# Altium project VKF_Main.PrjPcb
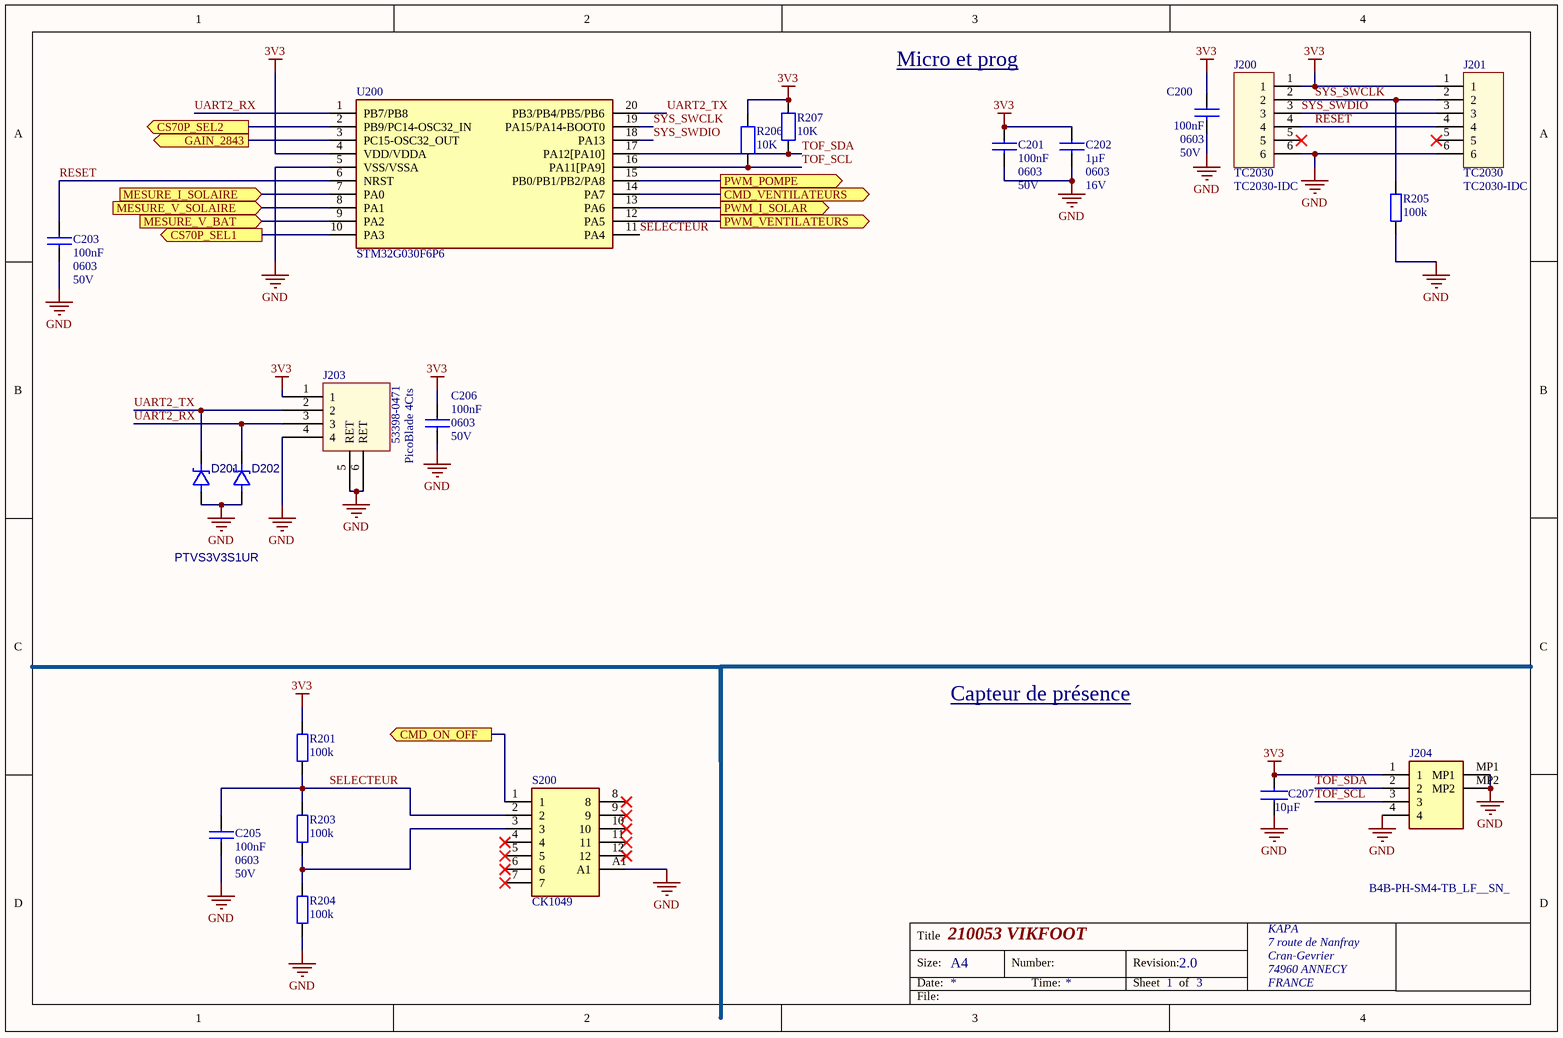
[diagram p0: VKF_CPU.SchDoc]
3 sheets, 104 parts. Net scope: flat (ports and power ports of the same name join across sheets).
Board file: VKF_PCB.PcbDoc
Sheets:
  VKF_CPU.SchDoc
  VKF_SOLAIRE.SchDoc
  VKF_ALIM.SchDoc

## Sheet VKF_CPU.SchDoc: DEV-09-17 MERE
size A4; Date: 22/11/2017; Organization: Altium Limited; Address1: L3, 12a Rodborough Rd; Address2: Frenchs Forest; Address3: NSW; Address4: Australia 2086; DocumentNumber: 4; Revision: 2.0; SheetNumber: 1; SheetTotal: 3; PageSetup: Record=PageOptions¦CenterHorizontal=True¦CenterVertical=True¦PrintScale=0.97¦XCorrection=1.00¦YCorrection=1.00¦PrintKind=0¦BorderSize=5000000¦LeftOffset=0¦BottomOffset=0¦Orientation=2¦PaperLength=1000¦PaperWidth=1000¦Scale=100¦PaperSource=7¦PrintQuality=-3¦MediaType=1¦DitherType=10¦PaperKind=A4¦PrintScaleMode=1

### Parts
C200  100nF  CASE: 0603  Voltage: 50V  [CAP0603]
C201  100nF  CASE: 0603  Voltage: 50V  [CAP0603]
C202  1µF  CASE: 0603  Voltage: 16V  [CAP0603]
C203  100nF  CASE: 0603  Voltage: 50V  [CAP0603]
C205  100nF  CASE: 0603  Voltage: 50V  [CAP0603]
C206  100nF  CASE: 0603  Voltage: 50V  [CAP0603]
C207  10µF  [CAP_0603_0H80]
D201  PTVS3V3S1UR  [SOD-123]
D202  PTVS3V3S1UR  [SOD-123]  (value not drawn)
J200  TC2030  CASE: TC2030-IDC  [TC2030-IDC-FP]
J201  TC2030  CASE: TC2030-IDC  [TC2030-IDC-FP]
J203  53398-0471  CASE: PicoBlade 4Cts  [CNT-S (MOLEX Ref SD-53398-0471)]
J204  B4B-PH-SM4-TB_LF__SN_  [B4B-PH-SM4_1]
R201  100k  [RES0603]
R203  100k  [RES0603]
R204  100k  [RES0603]
R205  100k  [RES0603]
R206  10K  [RES_0603_0H90]
R207  10K  [RES_0603_0H90]
S200  CK1049  [CK1059]
U200  STM32G030F6P6  [TSSOP20-0.65]

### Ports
CMD_ON_OFF (out, see VKF_SOLAIRE[1B]), CMD_VENTILATEURS (out, see VKF_ALIM[3B]), CS70P_SEL1 (out, see VKF_SOLAIRE[2A]), CS70P_SEL2 (out, see VKF_SOLAIRE[2A]), GAIN_2843 (out, see VKF_SOLAIRE[4C]), MESURE_I_SOLAIRE (in, see VKF_SOLAIRE[3A]), MESURE_V_BAT (in, see VKF_SOLAIRE[4A]), MESURE_V_SOLAIRE (in, see VKF_SOLAIRE[3A]), PWM_I_SOLAR (out, see VKF_SOLAIRE[2B]), PWM_POMPE (out, see VKF_ALIM[3C]), PWM_VENTILATEURS (out, see VKF_ALIM[3B])

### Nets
3V3: C200.1 C201.1 C202.1 C206.1 C207.2 J200.1 J201.1 J203.1 J204.1 R201.2 R206.2 R207.2 U200.4(VDD/VDDA)
GND: C200.2 C201.2 C202.2 C203.2 C205.2 C206.2 C207.1 D201.2(A) D202.2(A) J200.6 J201.6 J203.4 J203.5(RET) J203.6(RET) J204.4 J204.MP1 J204.MP2 R204.1 R205.1 S200.A1 U200.5(VSS/VSSA)
RESET: C203.1 J200.4 J201.4 U200.6(NRST)
SELECTEUR: C205.1 R201.1 R203.2 S200.2 U200.11(PA4)
SYS_SWCLK: J200.2 J201.2 R205.2 U200.19(PA15/PA14-BOOT0)
SYS_SWDIO: J200.3 J201.3 U200.18(PA13)
TOF_SCL: J204.3 R206.1 U200.16(PA11[PA9])
TOF_SDA: J204.2 R207.1 U200.17(PA12[PA10])
UART2_RX: D202.1(K) J203.3 U200.1(PB7/PB8)
UART2_TX: D201.1(K) J203.2 U200.20(PB3/PB4/PB5/PB6)
NetC300_1: U200.8(PA1) ; port MESURE_V_SOLAIRE
NetC301_1: U200.9(PA2) ; port MESURE_V_BAT
NetC303_1: U200.7(PA0) ; port MESURE_I_SOLAIRE
NetD302_3: S200.1 ; port CMD_ON_OFF
NetIC102_3: U200.15(PB0/PB1/PB2/PA8) ; port PWM_POMPE
NetIC300_2: U200.10(PA3) ; port CS70P_SEL1
NetIC300_3: U200.2(PB9/PC14-OSC32_IN) ; port CS70P_SEL2
NetQ101_1: U200.12(PA5) ; port PWM_VENTILATEURS
NetQ102_1: U200.14(PA7) ; port CMD_VENTILATEURS
NetR203_1: R203.1 R204.2 S200.3
NetR306_1: U200.13(PA6) ; port PWM_I_SOLAR
NetR312_2: U200.3(PC15-OSC32_OUT) ; port GAIN_2843

Not connected (* = marked no-connect by the designer): J200 5*; J201 5*; S200 4* 5* 6* 7* 8* 9* 10* 11* 12*

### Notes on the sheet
- Micro et prog
- Capteur de présence
- Title
- Size:
- Date:
- 210053 VIKFOOT
- A4
- Number:
- Time:
- Revision:
- Sheet
- of
- KAPA
- 7 route de Nanfray
- 74960 ANNECY
- Cran-Gevrier
- FRANCE
- File:

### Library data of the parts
C200 C201 C203 C205 C206 = C0603-100nF-X7R-50V: Capacitor, Ceramic, 100nF, 0603, 10%, 50V, X7R; Ref Fabricant: Generic
C202 = C0603-1µF-X7R-16V: Capacitor, Ceramic, 1µF, 0603, 10%, 16V, X7R; Ref Fabricant: Generic
C207 = capacitor
D201 D202 = PTVS3V3S1UR: Diode TVS, série PTVS, 3.3 V, SOD-123; Prix: 0.363 €; Fabricant: NXP; Fournisseur: Farnell; Ref Fournisseur: 1829253
J200 J201 = TC2030: Connector Sonde Probe, 6cts; Fabricant: TAG-CONNECT; Ref Fournisseur: none
J203 = CNT-MOLEX-PicoBlade-SMT-4cts: Connector PicoBlade Header, SMT, 4cts; Fabricant: MOLEX; Ref Fournisseur: 1125367; Fournisseur: Farnell
J204 = B4B-PH-SM4-TB_LF__SN_: Connector; Manufacturer_Name: JST (JAPAN SOLDERLESS TERMINALS); Manufacturer_Part_Number: B4B-PH-SM4-TB(LF)(SN)
R201 R203-R205 = R0603_100k_1%_1: Resistor, Thin Film, 100k, 1%, 65mW, 0603; Ref Fabricant: Generic; TCR: 100ppm/°C
R206 R207 = Resistor
S200 = CK1049: Switch; Manufacturer_Name: Lorlin
U200 = STM32G030F6P6: ARM Cortex-M0+ 32-bit MCU, 32 KB Flash, 8 KB Internal RAM, 20-pin TSSOP; Fabricant: STMicroelectronics; Ref Fournisseur: 511-STM32G030F6P6; Fournisseur: Mouser

## Sheet VKF_SOLAIRE.SchDoc: DEV-09-17 MERE
size A4; Date: 22/11/2017; Organization: Altium Limited; Address1: L3, 12a Rodborough Rd; Address2: Frenchs Forest; Address3: NSW; Address4: Australia 2086; DocumentNumber: 4; Revision: 2.0; SheetNumber: 2; SheetTotal: 3; PageSetup: Record=PageOptions¦CenterHorizontal=True¦CenterVertical=True¦PrintScale=0.97¦XCorrection=1.00¦YCorrection=1.00¦PrintKind=0¦BorderSize=5000000¦LeftOffset=0¦BottomOffset=0¦Orientation=2¦PaperLength=1000¦PaperWidth=1000¦Scale=100¦PaperSource=7¦PrintQuality=-3¦MediaType=1¦DitherType=10¦PaperKind=A4¦PrintScaleMode=1
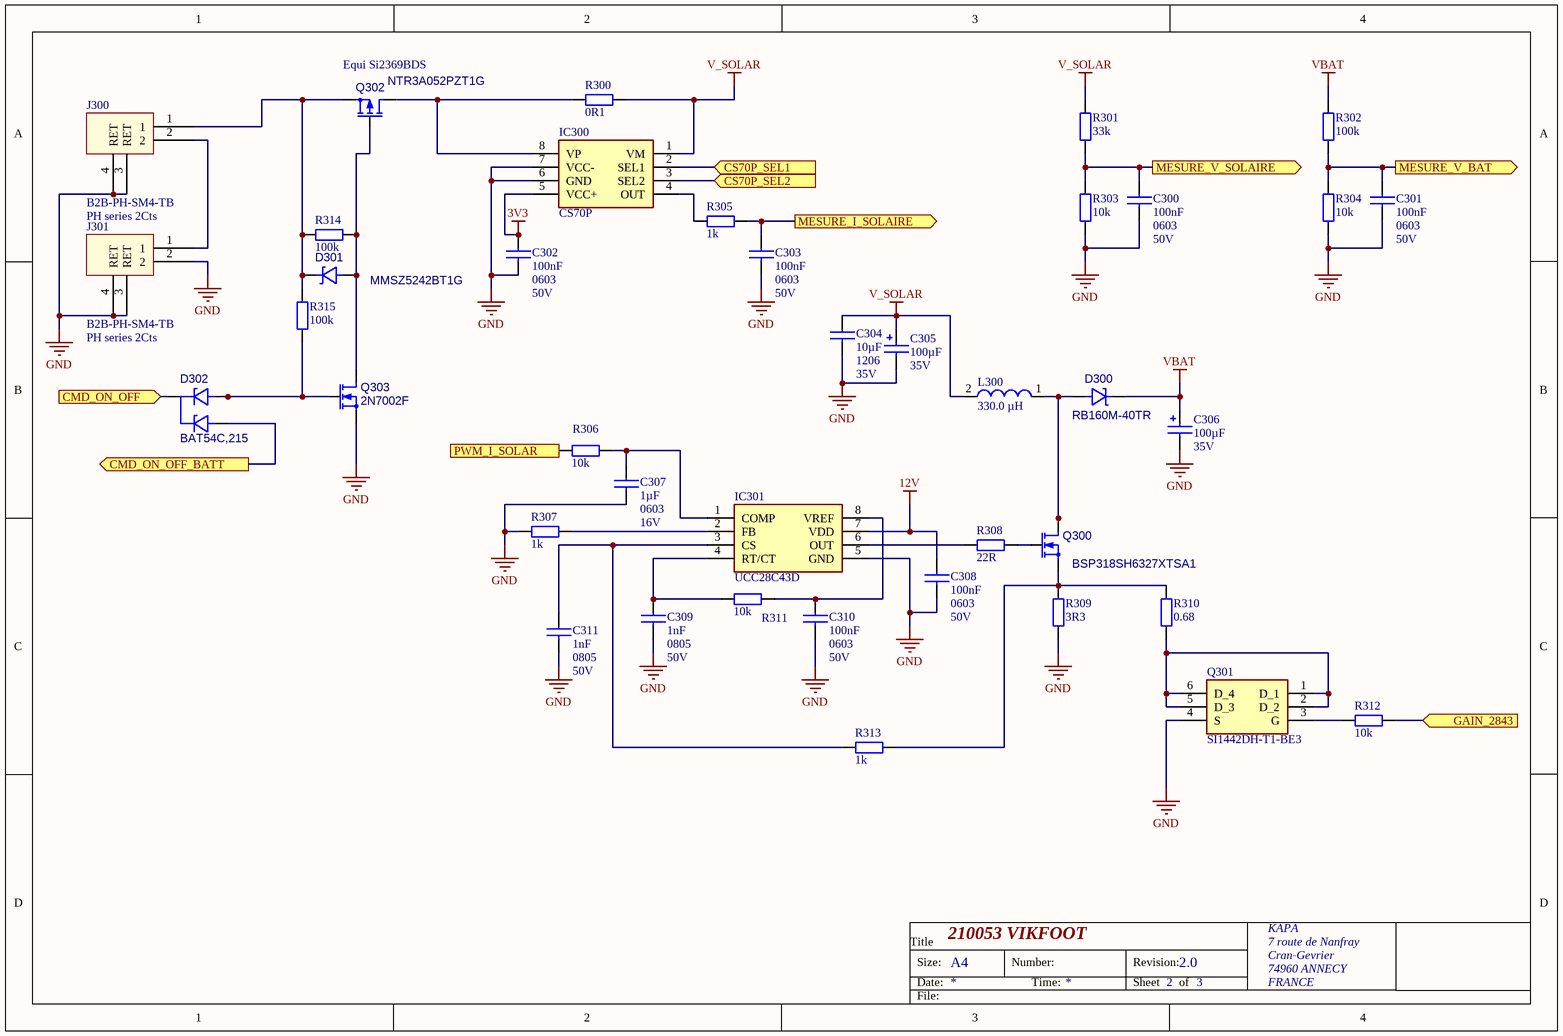
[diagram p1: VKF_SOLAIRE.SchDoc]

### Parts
C300  100nF  CASE: 0603  Voltage: 50V  [CAP0603]
C301  100nF  CASE: 0603  Voltage: 50V  [CAP0603]
C302  100nF  CASE: 0603  Voltage: 50V  [CAP0603]
C303  100nF  CASE: 0603  Voltage: 50V  [CAP0603]
C304  10µF  CASE: 1206  Voltage: 35V  [CAP1206]
C305  100µF  Voltage: 35V  [CP_D8]
C306  100µF  Voltage: 35V  [CP_D8]
C307  1µF  CASE: 0603  Voltage: 16V  [CAP0603]
C308  100nF  CASE: 0603  Voltage: 50V  [CAP0603]
C309  1nF  CASE: 0805  Voltage: 50V  [CAP0805]
C310  100nF  CASE: 0603  Voltage: 50V  [CAP0603]
C311  1nF  CASE: 0805  Voltage: 50V  [CAP0805]
D300  RB160M-40TR  [SOD-123]
D301  MMSZ5242BT1G  [SOD-123]
D302  BAT54C,215  [SOT23]
IC300  CS70P  [SOP65P640X120-8N]
IC301  UCC28C43D  [SOIC127P600X175-8N]
J300  B2B-PH-SM4-TB  CASE: PH series 2Cts  [CNT-S (JST Ref B2B-PH-SM4)]
J301  B2B-PH-SM4-TB  CASE: PH series 2Cts  [CNT-S (JST Ref B2B-PH-SM4)]
L300  330.0 µH  [WE-PD-M-PB]
Q300  BSP318SH6327XTSA1  [ONSC-SOT-223-4-318E-04_V]
Q301  SI1442DH-T1-BE3  [SOT65P210X110-6N]
Q302  NTR3A052PZT1G  [SOT23]
Q303  2N7002F  [SOT23]
R300  0R1  [RES0805]
R301  33k  [RES0603]
R302  100k  [RES0603]
R303  10k  [RES0603]
R304  10k  [RES0603]
R305  1k  [RES0805]
R306  10k  [RES0805]
R307  1k  [RES0805]
R308  22R  [RES0805]
R309  3R3  [RES0805]
R310  0.68  [RES1206]
R311  10k  [RES0805]
R312  10k  [RES0603]
R313  1k  [RES0805]
R314  100k  [RES0603]
R315  100k  [RES0603]

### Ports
CMD_ON_OFF (in, see VKF_CPU[1C]), CMD_ON_OFF_BATT (out, see VKF_ALIM[1D]), CS70P_SEL1 (in, see VKF_CPU[1A]), CS70P_SEL2 (in, see VKF_CPU[1A]), GAIN_2843 (in, see VKF_CPU[1A]), MESURE_I_SOLAIRE (out, see VKF_CPU[1A]), MESURE_V_BAT (out, see VKF_CPU[1A]), MESURE_V_SOLAIRE (out, see VKF_CPU[1A]), PWM_I_SOLAR (in, see VKF_CPU[2A])

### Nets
3V3: C302.1 IC300.5(VCC+)
12V: C308.1 IC301.7(VDD)
GND: C300.2 C301.2 C302.2 C303.2 C304.2 C305.2 C306.2 C307.2 C308.2 C309.2 C310.2 C311.2 IC300.6(GND) IC300.7(VCC-) IC301.5(GND) J300.3(RET) J300.4(RET) J301.2 J301.3(RET) J301.4(RET) Q301.4(S) Q303.2(S) R303.1 R304.1 R307.1 R309.1
V_SOLAR: C304.1 C305.1 IC300.1(VM) L300.2 R300.2 R301.2
VBAT: C306.1 D300.1(K) R302.2
NetC300_1: C300.1 R301.1 R303.2 ; port MESURE_V_SOLAIRE
NetC301_1: C301.1 R302.1 R304.2 ; port MESURE_V_BAT
NetC303_1: C303.1 R305.2 ; port MESURE_I_SOLAIRE
NetC307_1: C307.1 IC301.1(COMP) R306.2
NetC309_1: C309.1 IC301.4(RT/CT) R311.1
NetC310_1: C310.1 IC301.8(VREF) R311.2
NetC311_1: C311.1 IC301.3(CS) R313.1
NetD300_2: D300.2(A) L300.1 Q300.2(D) Q300.4(D)
NetD301_1: D301.1(K) J300.1 Q302.2(S) R314.2 R315.2
NetD301_2: D301.2(A) Q302.1(G) Q303.3(D) R314.1
NetD302_1: D302.1(K1) Q303.1(G) R315.1
NetD302_2: D302.2(K2) ; port CMD_ON_OFF_BATT
NetD302_3: D302.3(A) ; port CMD_ON_OFF
NetIC300_2: IC300.2(SEL1) ; port CS70P_SEL1
NetIC300_3: IC300.3(SEL2) ; port CS70P_SEL2
NetIC300_4: IC300.4(OUT) R305.1
NetIC300_8: IC300.8(VP) Q302.3(D) R300.1
NetIC301_2: IC301.2(FB) R307.2
NetIC301_6: IC301.6(OUT) R308.1
NetJ300_2: J300.2 J301.1
NetQ300_1: Q300.1(G) R308.2
NetQ300_3: Q300.3(S) R309.2 R310.2 R313.2
NetQ301_1: Q301.1(D_1) Q301.2(D_2) Q301.5(D_3) Q301.6(D_4) R310.1
NetQ301_3: Q301.3(G) R312.1
NetR306_1: R306.1 ; port PWM_I_SOLAR
NetR312_2: R312.2 ; port GAIN_2843

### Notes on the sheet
- (near Q302) Equi Si2369BDS
- Title
- Size:
- Date:
- 210053 VIKFOOT
- A4
- Number:
- Time:
- Revision:
- Sheet
- of
- KAPA
- 7 route de Nanfray
- 74960 ANNECY
- Cran-Gevrier
- FRANCE
- File:

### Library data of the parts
C300-C303 C308 C310 = C0603-100nF-X7R-50V: as C200 on sheet VKF_CPU
C304 = C1206-10µF-X7R-35V: Capacitor, Ceramic, 10µF, 1206, 10%, 35V, X7R; Ref Fabricant: Generic
C305 C306 = COND-EEEFPV101XAP: Capacitor, ALU, 100µF, Case D, 20%, 35V; Ref Fournisseur: 1539501; Fournisseur: Farnell; Fabricant: Panasonic
C307 = C0603-1µF-X7R-16V: as C202 on sheet VKF_CPU
C309 C311 = C0805-1nF-X7R-50V: Capacitor, Ceramic, 1nF, 0805, 10%, 50V, X7R; Ref Fabricant: Generic
D300 = RB160M-40TR: Diode Schottky, 1A, 40V, SOD-123; Fabricant: ROHM; Fournisseur: Farnell; Ref Fournisseur: 1680023
D301 = MMSZ5242BT1G: Zener, 12 V, 500 mW, SOD-123; Fabricant: ON SEMI; Fournisseur: Farnell; Ref Fournisseur: 1431281
D302 = BAT54C,215: Dual schottky Diode Common Chatode 30V 200mA SOT23; Fabricant: NEXPERIA; Fournisseur: MOUSER; Ref Fournisseur: 771-BAT54C-T/R
IC300 = CS70P: Integrated Circuit; Manufacturer_Name: STMicroelectronics
IC301 = UCC28C43D: Integrated Circuit; Manufacturer_Name: Texas Instruments
J300 J301 = CNT-JST-PH Series-SMT-2cts: Connector PH JST Header,Top Entry, SMT, 2cts; Ref Fournisseur: 9492534; Fournisseur: Farnell
L300 = WURTH-330µH-0.40A-7.3x7.3_1: SMD-Shielded Power Inductor WE-PD, L = 330.0 µH; Fabricant: WURTH ELEKTRONIK; Ref Fabricant: 7447783331; Fournisseur: Farnell; Ref Fournisseur: 3812837
Q300 = BSP318SH6327XTSA1: Transistor Mosfet, 2.6A, 60V, canal N, Logic level, SOT223; pin to pad: 2>2+4; Fabricant: INFINEON; Fournisseur: MOUSER; Ref Fournisseur: 726-BSP318SH6327XTSA
Q301 = SI1442DH-T1-BE3: Integrated Circuit; Manufacturer_Name: Vishay
Q302 = NTR3A052PZT1G: Mosfet Canal P, 3A, 20V, SOT23; Fabricant: ON SEMI; Fournisseur: MOUSER; Ref Fournisseur: 863-NTR3A052PZT1G
Q303 = 2N7002F: Transistor Mosfet 2N7002F, 385mA canal N, SOT23; Prix: 0.059 €; Fabricant: NXP; Fournisseur: Farnell; Ref Fournisseur: 1894722
R300 = R0805_0R1_1%: Resistor, Thin Film, 0R1, 1%, 125mW, 0805; Ref Fabricant: Generic; TCR: 100ppm/°C
R301 = R0603_33k_1%: Resistor, Thin Film, 33k, 1%, 65mW, 0603; Ref Fabricant: Generic; TCR: 100ppm/°C
R302 R314 R315 = R0603_100k_1%_1: as R201 on sheet VKF_CPU
R303 R304 R312 = R0603_10k_1%: Resistor, Thin Film, 10k, 1%, 65mW, 0603; Ref Fabricant: Generic; TCR: 100ppm/°C
R305 R307 R313 = R0805_1k_1%: Resistor, Thin Film, 1k, 1%, 125mW, 0805; Ref Fabricant: Generic; TCR: 100ppm/°C
R306 R311 = R0805_10k_1%: Resistor, Thin Film, 10k, 1%, 125mW, 0805; Ref Fabricant: Generic; TCR: 100ppm/°C
R308 = R0805_22R_1%: Resistor, Thin Film, 22R, 1%, 125mW, 0805; Ref Fabricant: Generic; TCR: 100ppm/°C
R309 = R0805_3R3_1%: Resistor, Thin Film, 3R3, 1%, 125mW, 0805; Ref Fabricant: Generic; TCR: 100ppm/°C
R310 = R1206_0.68_1%: Resistor, couche epaisse, 0.68, 1%, 500mW, 1206; Ref Fabricant: Generic; TCR: 100ppm/°C

## Sheet VKF_ALIM.SchDoc: DEV-09-17 MERE
size A4; Date: 22/11/2017; Organization: Altium Limited; Address1: L3, 12a Rodborough Rd; Address2: Frenchs Forest; Address3: NSW; Address4: Australia 2086; DocumentNumber: 4; Revision: 2.0; SheetNumber: 3; SheetTotal: 3; PageSetup: Record=PageOptions¦CenterHorizontal=True¦CenterVertical=True¦PrintScale=0.97¦XCorrection=1.00¦YCorrection=1.00¦PrintKind=0¦BorderSize=5000000¦LeftOffset=0¦BottomOffset=0¦Orientation=2¦PaperLength=1000¦PaperWidth=1000¦Scale=100¦PaperSource=7¦PrintQuality=-3¦MediaType=1¦DitherType=10¦PaperKind=A4¦PrintScaleMode=1
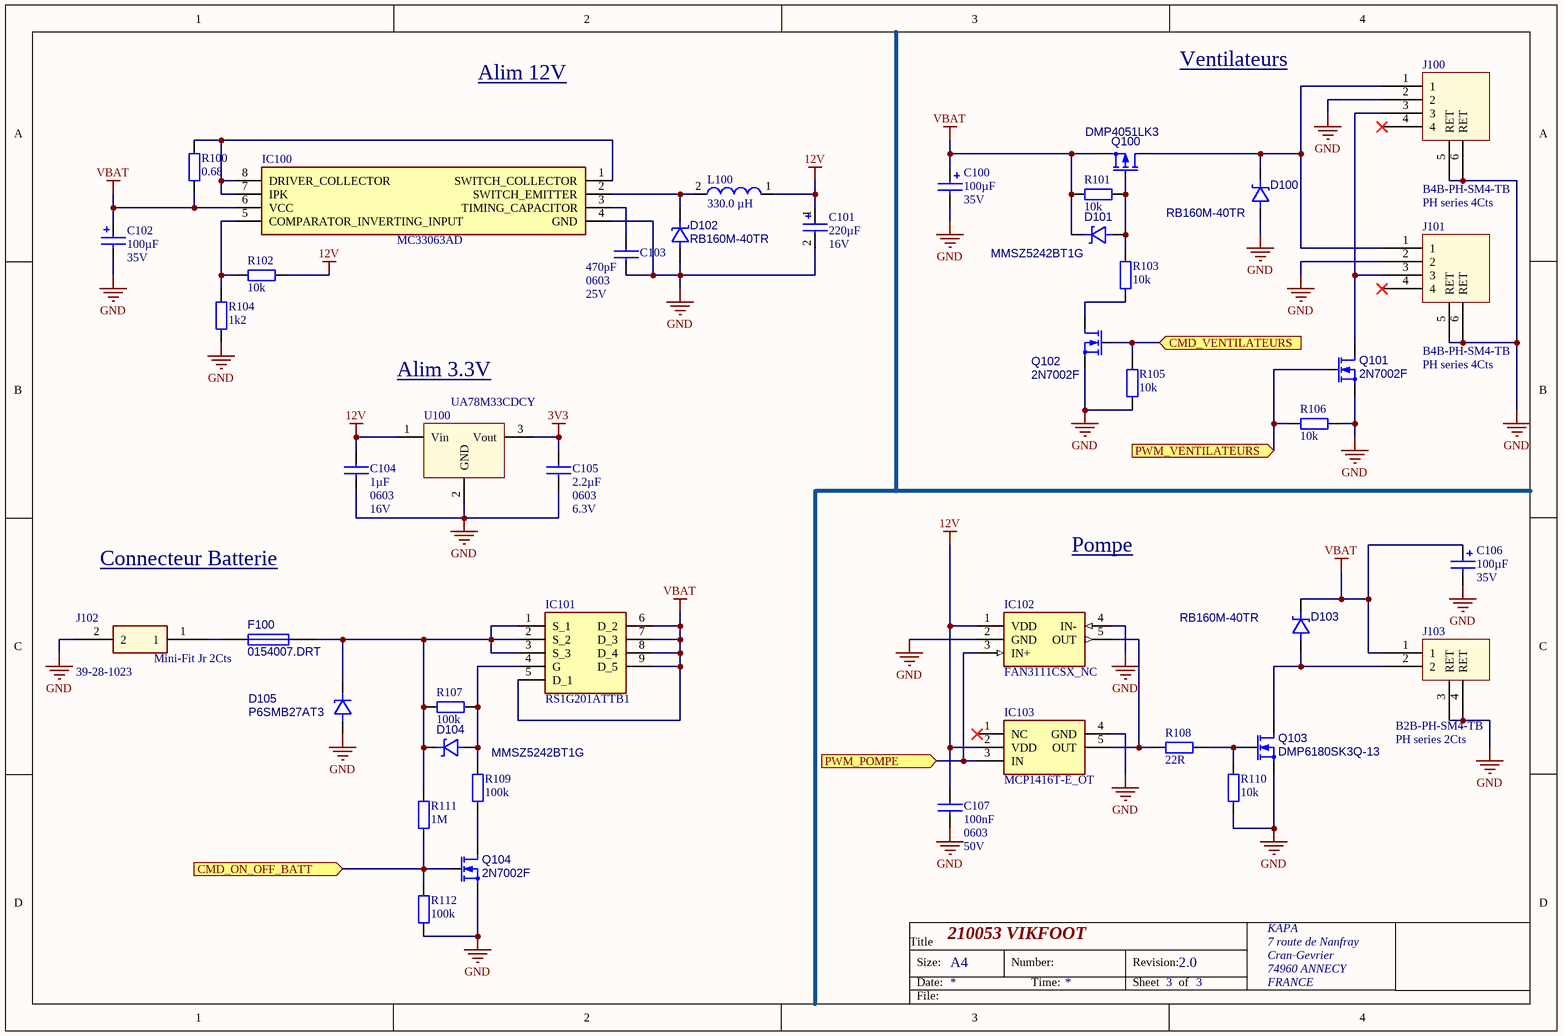
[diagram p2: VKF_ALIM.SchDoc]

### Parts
C100  100µF  Voltage: 35V  [CP_D8]
C101  220µF  Voltage: 16V  [CP_D8]
C102  100µF  Voltage: 35V  [CP_D8]
C103  470pF  CASE: 0603  Voltage: 25V  [CAP0603]
C104  1µF  CASE: 0603  Voltage: 16V  [CAP0603]
C105  2.2µF  CASE: 0603  Voltage: 6.3V  [CAP0603]
C106  100µF  Voltage: 35V  [CP_D8]
C107  100nF  CASE: 0603  Voltage: 50V  [CAP0603]
D100  RB160M-40TR  [SOD-123]
D101  MMSZ5242BT1G  [SOD-123]
D102  RB160M-40TR  [SOD-123]
D103  RB160M-40TR  [SOD-123]
D104  MMSZ5242BT1G  [SOD-123]
D105  P6SMB27AT3  [SMB]
F100  0154007.DRT  [0154]
IC100  MC33063AD  [SOIC127P600X175-8N]
IC101  RS1G201ATTB1  [RS1G201ATTB1]
IC102  FAN3111CSX_NC  [SOT95P280X145-5N]
IC103  MCP1416T-E_OT  [SOT95P270X145-5N]
J100  B4B-PH-SM4-TB  CASE: PH series 4Cts  [CNT-S (JST Ref B4B-PH-SM4)]
J101  B4B-PH-SM4-TB  CASE: PH series 4Cts  [CNT-S (JST Ref B4B-PH-SM4)]
J102  39-28-1023  [CNT-T (MOLEX Ref 39-31-0020)]
J103  B2B-PH-SM4-TB  CASE: PH series 2Cts  [CNT-S (JST Ref B2B-PH-SM4)]
L100  330.0 µH  [WE-PD-M-PB]
Q100  DMP4051LK3  [DPAK]
Q101  2N7002F  [SOT23]
Q102  2N7002F  [SOT23]
Q103  DMP6180SK3Q-13  [TO-252_DPAK_3P]
Q104  2N7002F  [SOT23]
R100  0.68  [RES1206]
R101  10k  [RES0603]
R102  10k  [RES0603]
R103  10k  [RES0603]
R104  1k2  [RES0603]
R105  10k  [RES0603]
R106  10k  [RES0603]
R107  100k  [RES0603]
R108  22R  [RES0805]
R109  100k  [RES0603]
R110  10k  [RES0603]
R111  1M  [RES0603]
R112  100k  [RES0603]
U100  UA78M33CDCY  [SOT223_MOSFET]

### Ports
CMD_ON_OFF_BATT (in, see VKF_SOLAIRE[1B]), CMD_VENTILATEURS (in, see VKF_CPU[2A]), PWM_POMPE (in, see VKF_CPU[2A]), PWM_VENTILATEURS (in, see VKF_CPU[2A])

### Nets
3V3: C105.1 U100.3(Vout)
12V: C101.1 C104.1 C107.1 IC102.1(VDD) IC103.2(VDD) L100.1 R102.2 U100.1(Vin)
GND: C100.2 C101.2 C102.2 C103.2 C104.2 C105.2 C106.2 C107.2 D100.2(A) D102.2(A) D105.2(A) IC100.4(GND) IC102.2(GND) IC102.4(IN-) IC103.4(GND) J100.2 J100.5(RET) J100.6(RET) J101.2 J101.5(RET) J101.6(RET) J102.2 J103.3(RET) J103.4(RET) Q101.2(S) Q102.2(S) Q103.3(S) Q104.2(S) R104.1 R105.2 R106.1 R110.2 R112.1 U100.2(GND)
VBAT: C100.1 C102.1 C106.1 D101.1(K) D103.1(K) IC100.6(VCC) IC101.5(D_1) IC101.6(D_2) IC101.7(D_3) IC101.8(D_4) IC101.9(D_5) J103.1 Q100.3(S) R100.1 R101.1
NetC103_1: C103.1 IC100.3(TIMING_CAPACITOR)
NetD100_1: D100.1(K) J100.1 J101.1 Q100.2(D)
NetD101_2: D101.2(A) Q100.1(G) R101.2 R103.2
NetD102_1: D102.1(K) IC100.2(SWITCH_EMITTER) L100.2
NetD103_2: D103.2(A) J103.2 Q103.2(D)
NetD104_1: D104.1(K) D105.1(K) F100.2 IC101.1(S_1) IC101.2(S_2) IC101.3(S_3) R107.2 R111.2
NetD104_2: D104.2(A) IC101.4(G) R107.1 R109.2
NetD302_2: Q104.1(G) R111.1 R112.2 ; port CMD_ON_OFF_BATT
NetF100_1: F100.1 J102.1
NetIC100_1: IC100.1(SWITCH_COLLECTOR) IC100.7(IPK) IC100.8(DRIVER_COLLECTOR) R100.2
NetIC100_5: IC100.5(COMPARATOR_INVERTING_INPUT) R102.1 R104.2
NetIC102_3: IC102.3(IN+) IC103.3(IN) ; port PWM_POMPE
NetIC102_5: IC102.5(OUT) IC103.5(OUT) R108.1
NetJ100_3: J100.3 J101.3 Q101.3(D)
NetQ101_1: Q101.1(G) R106.2 ; port PWM_VENTILATEURS
NetQ102_1: Q102.1(G) R105.1 ; port CMD_VENTILATEURS
NetQ102_3: Q102.3(D) R103.1
NetQ103_1: Q103.1(G) R108.2 R110.1
NetQ104_3: Q104.3(D) R109.1

Not connected (* = marked no-connect by the designer): IC103 1(NC)*; J100 4*; J101 4*

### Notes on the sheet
- Alim 12V
- Ventilateurs
- Alim 3.3V
- Connecteur Batterie
- Pompe
- Title
- Size:
- Date:
- 210053 VIKFOOT
- A4
- Number:
- Time:
- Revision:
- Sheet
- of
- KAPA
- 7 route de Nanfray
- 74960 ANNECY
- Cran-Gevrier
- FRANCE
- File:

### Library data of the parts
C100 C102 C106 = COND-EEEFPV101XAP: as C305 on sheet VKF_SOLAIRE
C101 = COND-EEEFK1C221XP: Capacitor, ALU, 220µF, Case D, 20%, 16V; Ref Fournisseur: 1850103; Fournisseur: Farnell; Fabricant: Panasonic
C103 = C0603-470pF-X7R-25V: Capacitor, Ceramic, 470pF, 0603, 10%, 25V, X7R; Ref Fabricant: Generic
C104 = C0603-1µF-X7R-16V: as C202 on sheet VKF_CPU
C105 = C0603-2.2µF-X7R-6.3V: Capacitor, Ceramic, 2.2µF, 0603, 10%, 6.3V, X7R; Ref Fabricant: Generic
C107 = C0603-100nF-X7R-50V: as C200 on sheet VKF_CPU
D100 D102 D103 = RB160M-40TR: as D300 on sheet VKF_SOLAIRE
D101 D104 = MMSZ5242BT1G: as D301 on sheet VKF_SOLAIRE
D105 = P6SMB27AT3_SMB: Diode Transil Unidirectionnelle, série P6SMB27AT3, 27 V, SMB; Prix: 0.17 €; Fabricant: ON SEMICONDUCTOR; Fournisseur: Farnell; Ref Fournisseur: 1611366
F100 = 0154007.DRT: Surface Mount Fuses and holder. NANO 7A; Fabricant: LITTELFUSE; Fournisseur: Farnell; Ref Fournisseur: 2383265
IC100 = MC33063AD: Integrated Circuit; Manufacturer_Name: Texas Instruments
IC101 = RS1G201ATTB1: Integrated Circuit; Manufacturer_Name: ROHM Semiconductor
IC102 = FAN3111CSX: Integrated Circuit; Manufacturer_Name: ON Semiconductor
IC103 = MCP1416T-E_OT: Integrated Circuit; Manufacturer_Name: Microchip; Manufacturer_Part_Number: MCP1416T-E/OT
J100 J101 = CNT-JST-PH Series-SMT-4cts: Connector PH JST Header,Top Entry, SMT, 5cts; Ref Fournisseur: 9491929; Fournisseur: Farnell
J102 = CNT-MOLEX-Mini-Fit Jr-2cts: Connector MOLEX Mini-Fit Jr, Top Entry, 2cts; Ref Fournisseur: 9732080; Fournisseur: Farnell
J103 = CNT-JST-PH Series-SMT-2cts: as J300 on sheet VKF_SOLAIRE
L100 = WURTH-330µH-0.40A-7.3x7.3_1: as L300 on sheet VKF_SOLAIRE
Q100 = DMP4051LK3: Mosfet Canal P, 10A, 40V, DPAK; Fabricant: DIODE INCOR; Fournisseur: MOUSER; Ref Fournisseur: 621-DMP4051LK3-13
Q101 Q102 Q104 = 2N7002F: as Q303 on sheet VKF_SOLAIRE
Q103 = IPD135N03L: Transistor Mosfet DMP6180SK3Q-13, canal N, TO-252_DPAK, 10A 60V; Fabricant: DIODE INC; Ref Fournisseur: 621-DMP6180SK3Q-13; FOURNISSEUR: MOUSER
R100 = R1206_0.68_1%: as R310 on sheet VKF_SOLAIRE
R101-R103 R105 R106 R110 = R0603_10k_1%: as R303 on sheet VKF_SOLAIRE
R104 = R0603_1k2_1%: Resistor, Thin Film, 1k2, 1%, 65mW, 0603; Ref Fabricant: Generic; TCR: 100ppm/°C
R107 R109 R112 = R0603_100k_1%_1: as R201 on sheet VKF_CPU
R108 = R0805_22R_1%: as R308 on sheet VKF_SOLAIRE
R111 = R0603_1M_1%: Resistor, Thin Film, 1M, 1%, 65mW, 0603; Ref Fabricant: Generic; TCR: 100ppm/°C
U100 = UA78M33CDCY: Regulateur LDO 3.3V, 500mA; Fabricant: Texas Instruments; Prix: 0,461€; Fournisseur: Farnell; Ref Fournisseur: 2296031

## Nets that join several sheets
3V3: VKF_CPU (13 pins), VKF_SOLAIRE (C302.1 IC300.5), VKF_ALIM (C105.1 U100.3)
12V: VKF_SOLAIRE (C308.1 IC301.7), VKF_ALIM (8 pins)
GND: VKF_CPU (21 pins), VKF_SOLAIRE (26 pins), VKF_ALIM (34 pins)
VBAT: VKF_SOLAIRE (C306.1 D300.1 R302.2), VKF_ALIM (15 pins)
NetC300_1: VKF_CPU (U200.8), VKF_SOLAIRE (C300.1 R301.1 R303.2)
NetC301_1: VKF_CPU (U200.9), VKF_SOLAIRE (C301.1 R302.1 R304.2)
NetC303_1: VKF_CPU (U200.7), VKF_SOLAIRE (C303.1 R305.2)
NetD302_2: VKF_SOLAIRE (D302.2), VKF_ALIM (Q104.1 R111.1 R112.2)
NetD302_3: VKF_CPU (S200.1), VKF_SOLAIRE (D302.3)
NetIC102_3: VKF_CPU (U200.15), VKF_ALIM (IC102.3 IC103.3)
NetIC300_2: VKF_CPU (U200.10), VKF_SOLAIRE (IC300.2)
NetIC300_3: VKF_CPU (U200.2), VKF_SOLAIRE (IC300.3)
NetQ101_1: VKF_CPU (U200.12), VKF_ALIM (Q101.1 R106.2)
NetQ102_1: VKF_CPU (U200.14), VKF_ALIM (Q102.1 R105.1)
NetR306_1: VKF_CPU (U200.13), VKF_SOLAIRE (R306.1)
NetR312_2: VKF_CPU (U200.3), VKF_SOLAIRE (R312.2)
